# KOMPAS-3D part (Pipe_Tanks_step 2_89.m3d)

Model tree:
1. X Axis
2. Y Axis
3. Z Axis  (labels: Valve Dy 50; Pipe Dn 50)
     Òîëùèíà ñòåíêè 1 = 1

Referenced files in C:\Documents and Settings\kashirsky\Мои документы\Camtasia Studio\Pipelines3D\Tanks\: Tanks_step 4.a3d
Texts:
  Pipe Dn 50
  Steel ASTM A295
  Three Point Plane
  Plane at Angle
  Line and Point Plane
  Axis through Two Vertices
  Axis of Feature
  Axis of Conical Surface
  Axis through Edge
  Trim by Surface
  Trim by Sketch
  Feature with No History
  Intersection Axis of Two Planes
  Two Line Plane
  Line and Face Plane
  Bend by line
  Hole in sheet body
  Cut in sheet body
  Point in CM
  Linear Dimension from Line to Point
  Surface Finish Symbol
  Geometric Tolerance Symbol
  Leader #1
  Leader #2
  Leader #3
  Shape Deviations and Datum
  Node point number
  Mark of coordination axis
  Node point designation
  Mark/Reference designation with leader
  Mark/reference designation on line
  Mark/Reference designation without leader
  Valve Dy 50
  Plane of section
